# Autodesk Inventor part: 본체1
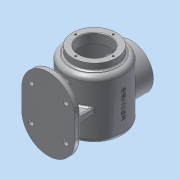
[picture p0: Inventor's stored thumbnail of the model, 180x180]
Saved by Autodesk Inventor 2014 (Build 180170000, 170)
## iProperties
Created: 2023-01
Part Number: 본체1
Material: 알루미늄 6061
Document SubType Name: Modeling
Designer: dg
Density: 2.71 g/cm^3
Appearance: 알루미늄 - 평지
Mass: 1027.11 g
Surface Area: 1161.19 cm^2
Volume: 379.006 cm^3
Author: dg
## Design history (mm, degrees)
sketch "스케치1"
  geometry: C1 r 50 at (0, 0); 1 further point
  constraints: 1 centre point, 1 coincident
  dimensions: "d0" = 100 diameter of C1
extrude "돌출1" new body sketch "스케치1" stored distance "d1" = 122; taper "d2" = 0 deg
sketch "스케치2"
  geometry: L1 (50, -61)-(-50, -61) reference; L2 (-50, -61)-(-50, 61) reference; L3 (-50, 61)-(50, 61) reference; L4 (50, 61)-(50, -61) reference; L5 (0, 61)-(0, -61); L6 (50, -50.087)-(50, -61); L7 (50, -61)-(0, -61); A1 r 120 centre (0, 59) between (0, -61) and (50, -50.087); 1 further point
  constraints: 6 end point, 3 midpoint, 2 collinear, 2 point on circle, 2 point on line, 2 tangent, 1 centre point
  dimensions: "d3" = 240 diameter of A1
revolve "회전1" sketch "스케치2" stored, may be unused: angle "d4" = 90 deg
sketch "스케치3"
  geometry: L1 (-50, -50.087)-(-50, 61) reference; L2 (-50, 61)-(50, 61) reference; L3 (50, 61)-(50, -50.087) reference; L4 (0, 61)-(0, -61); L5 (50, 49)-(38, 49); L6 (38, 49)-(38, 61); L7 (50, 49)-(50, 61); L8 (50, 61)-(38, 61); L9 (27, 61)-(27, 44); L10 (27, 44)-(42, 44); L11 (45, 41)-(45, -45.202); L12 (50, -50.087)-(-50, -50.087) reference; L13 (27, 61)-(0, 61); A1 r 120 centre (0, 59) between (0, -61) and (50, -50.087) reference; A2 r 120 centre (0, 59) between (-50, -50.087) and (0, -61) reference; A3 r 3 centre (42, 41) between (45, 41) and (42, 44); A4 r 120 centre (0, 64) between (0, -56) and (43.077, -48.002); A5 r 3 centre (42, -45.202) between (43.077, -48.002) and (45, -45.202); 2 further points
  constraints: 18 end point, 7 point on circle, 6 point on line, 4 perpendicular, 4 tangent, 3 centre point, 3 parallel, 2 collinear, 1 midpoint
  dimensions: "d5" = 76 diameter of L6 L4; "d6" = 110 distance from line of L4.end L5; "d10" = 90 diameter of L11 L4; "d11" = 17 distance between parallel lines of L2 L10; "d12" = 54 diameter of L9 L4; "d103" = 120 radius of A4; "d104" = 125 distance of L4.end A4.centre; "d105" = 3 radius of A5; "d106" = 3 radius of A3
revolve "회전2" sketch "스케치3" stored, may be unused: angle "d16" = 90 deg
chamfer "모따기1" distance "d17" = 1; stored, may be unused: second distance "d18" = 2, angle "d19" = 45 deg
fillet "모깎기1" dims "d20" = 8
fillet "모깎기2" dims "d21" = 3
node "작업 평면1"
sketch "스케치4"
  geometry: 1 further point
node "작업 평면2"
sketch "스케치5"
  geometry: L1 (38, 61)-(-38, 61) reference; C1 r 38 at (0, -2); A1 r 120 centre (0, 59) between (-45, -52.243) and (45, -52.243) reference; 1 further point
  constraints: 1 centre point, 1 vertical alignment
  dimensions: "d24" = 63 distance from line of C1.centre L1; "d25" = 76 diameter of C1
extrude "돌출2" join sketch "스케치5" stored distance "d26" = 122; taper "d27" = 0 deg
sketch "스케치6"
  geometry: L1 (0, 15)-(0, -19); L2 (-46, 15)-(-46, -19); L3 (46, -19)-(46, 15); L4 (-35, 3)-(35, 3); L5 (35, 3)-(35, -7); L6 (35, -7)-(-35, -7); L7 (-35, -7)-(-35, 3); L8 (-35, 3)-(35, -7); L9 (35, 3)-(-35, -7); C1 r 38 at (0, -2) reference; C2 r 38 at (0, -2) reference; A1 r 46 centre (0, 15) between (46, 15) and (-46, 15); A2 r 46 centre (0, -19) between (-46, -19) and (46, -19); 1 further point
  constraints: 20 end point, 4 point on circle, 4 tangent, 3 midpoint, 3 parallel, 2 centre point, 1 horizontal, 1 perpendicular, 1 vertical
  dimensions: "d31" = 92 distance between parallel lines of L2 L3; "d32" = 70 distance between parallel lines of L7 L5; "d33" = 10 distance of L4.end L5.end; "d34" = 34 distance of L3.start L3.end
extrude "돌출3" join sketch "스케치6" distance "d35" = 10; taper "d36" = 0 deg
fillet "모깎기3" dims "d37" = 3
sketch "스케치7"
  geometry: L1 (-35, -3)-(35, -3); L2 (35, -3)-(35, 7); L3 (35, 7)-(-35, 7); L4 (-35, 7)-(-35, -3); L5 (-35, -3)-(35, 7); L6 (35, -3)-(-35, 7); C1 r 38 at (0, 2) reference; 1 further point
  constraints: 12 end point, 2 parallel, 1 coincident, 1 horizontal, 1 midpoint, 1 perpendicular
  dimensions: "d38" = 10 distance between parallel lines of L1 L3; "d39" = 70 distance of L1.start L1.end
extrude "돌출4" join sketch "스케치7" stored distance "d40" = 10; taper "d41" = 0 deg
sketch "스케치9"
  geometry: L1 (-70, 58)-(-70, 3) reference; L2 (-70, 3)-(-50, 3) reference; L3 (-50, 3)-(-50, 41) reference; L4 (-42, 49)-(-41, 49) reference; L5 (-38, 52)-(-38, 61) reference; L6 (-38, 61)-(-28, 61) reference; L7 (-28, 61)-(-27, 60) reference; L8 (-27, 60)-(-27, 44) reference; L9 (-27, 44)-(-42, 44) reference; L10 (-45, 41)-(-45, -45.202) reference; L11 (45, -45.202)-(45, 41) reference; L12 (42, 44)-(27, 44) reference; L13 (27, 44)-(27, 60) reference; L14 (27, 60)-(28, 61) reference; L15 (28, 61)-(38, 61) reference; L16 (38, 61)-(38, 52) reference; L17 (41, 49)-(42, 49) reference; L18 (50, 41)-(50, 36) reference; L19 (50, 36)-(64, 36) reference; L20 (64, 36)-(64, -40) reference; L21 (64, -40)-(50, -40) reference; L22 (50, -40)-(50, -44.827) reference; L23 (-50, -44.827)-(-50, -7) reference; L24 (-50, -7)-(-70, -7) reference; L25 (-70, -7)-(-70, -62) reference; L26 (-73, -65)-(-80, -65) reference; L27 (-80, -65)-(-80, 61) reference; L28 (-80, 61)-(-73, 61) reference; L29 (-50, 32.641)-(-70, 38); A1 r 3 centre (-73, 58) between (-70, 58) and (-73, 61) reference; A2 r 8 centre (-42, 41) between (-42, 49) and (-50, 41) reference; A3 r 3 centre (-41, 52) between (-41, 49) and (-38, 52) reference; A4 r 3 centre (-42, 41) between (-42, 44) and (-45, 41) reference; A5 r 3 centre (42, 41) between (45, 41) and (42, 44) reference; A6 r 3 centre (41, 52) between (38, 52) and (41, 49) reference; A7 r 8 centre (42, 41) between (50, 41) and (42, 49) reference; A8 r 8 centre (42, -44.827) between (45, -52.243) and (50, -44.827) reference; A9 r 120 centre (0, 59) between (-45, -52.243) and (0, -61) reference; A10 r 120 centre (0, 59) between (0, -61) and (45, -52.243) reference; A11 r 8 centre (-42, -44.827) between (-50, -44.827) and (-45, -52.243) reference; A12 r 3 centre (-73, -62) between (-73, -65) and (-70, -62) reference; A13 r 3 centre (-42, -45.202) between (-45, -45.202) and (-43.077, -48.002) reference; A14 r 120 centre (0, 64) between (-43.077, -48.002) and (0, -56) reference; A15 r 120 centre (0, 64) between (0, -56) and (43.077, -48.002) reference; A16 r 3 centre (42, -45.202) between (43.077, -48.002) and (45, -45.202) reference; 1 further point
  constraints: 2 end point, 2 point on line
  dimensions: "d42" = 105 deg angle of L1 L29; "d98" = 23 distance from line of L28 L29.end
feature "리브1" sketch "스케치9" dims "d44" = 1, "d45" = 10, "d46" = 0, "d47" = 0, "d48" = 1, "d49" = 1
node "작업 평면3"
sketch "스케치10"
  geometry: C1 r 38 at (0, 0) reference; C2 r 27 at (0, 0); 1 further point
  constraints: 1 centre point, 1 coincident
  dimensions: "d51" = 54 diameter of C2
extrude "돌출5" cut sketch "스케치10" stored distance "d52" = 10; taper "d53" = 0 deg
sketch "스케치11" dims "d54" = 65
  geometry: C1 r 27 at (0, 0) reference; C2 r 38 at (0, 0) reference; C3 r 3.218 at (0, 32.5); 2 further points
  constraints: 2 vertical alignment, 1 centre point, 1 coincident, 2 other
hole "구멍1" sketch "스케치11" at (0, 32.5) diameter "d55" = 3.242; stored, may be unused: countersink angle "d59" = 90 deg, drill point angle "d61" = 118 deg; dims "d56" = 8, "d57" = 4, "d58" = 2, "d60" = 10
sketch "스케치12" dims "d65" = 65
  geometry: C1 r 38 at (0, 0) reference; C2 r 28 at (0, 0) reference; C3 r 3.222 at (0, 32.5); 1 further point
  constraints: 2 vertical alignment, 1 centre point, 1 coincident, 2 other
hole "구멍2" sketch "스케치12" at (0, 32.5) diameter "d66" = 3.242; stored, may be unused: countersink angle "d70" = 90 deg, drill point angle "d72" = 118 deg; dims "d67" = 8, "d68" = 4, "d69" = 2, "d71" = 10
fillet "모깎기4" dims "d76" = 3
fillet "모깎기5" dims "d77" = 3
chamfer "모따기2" distance "d78" = 1; stored, may be unused: second distance "d79" = 2, angle "d80" = 45 deg
node "작업 평면4"
sketch "스케치13"
  geometry: L1 (38, 61)-(-38, 61) reference; L2 (-80, -65)-(-80, -19) reference; 2 further points
  constraints: 1 other
  dimensions: "d82" = 63 distance from line of L1 point (0, -2); "d83" = 80 distance from line of L2 point (0, -2)
feature "엠보싱1" sketch "스케치13" dims "d5" = 76, "d6" = 110, "d10" = 90, "d11" = 17, "d12" = 54, "d84" = 0.5, "d85" = 0, "d103" = 120, "d104" = 125, "d105" = 3, "d106" = 3
sketch "스케치14"
  geometry: C1 r 4.5 at (-30, -30); C2 r 4.5 at (-30, 30); C3 r 4.5 at (30, -30); C4 r 4.5 at (30, 30); 1 further point
  constraints: 4 centre point, 3 equal radius
  dimensions: "d86" = 30 horizontal distance of point (0, 0) C1.centre; "d87" = 30 horizontal distance of point (0, 0) C1.centre; "d88" = 9 diameter of C1; "d89" = 30 horizontal distance of C2.centre point (0, 0); "d90" = 30 horizontal distance of point (0, 0) C2.centre; "d91" = 30 horizontal distance of point (0, 0) C3.centre; "d92" = 30 horizontal distance of point (0, 0) C3.centre; "d93" = 30 horizontal distance of point (0, 0) C4.centre; "d94" = 30 horizontal distance of point (0, 0) C4.centre
extrude "돌출6" cut sketch "스케치14" distance "d95" = 10; taper "d96" = 0 deg
node "작업 평면5"
fillet "모깎기6" dims "d99" = 3
fillet "모깎기7" dims "d100" = 3
node "솔리드1"
pattern_circular "원형 패턴1" dims angle "d63" = 360 deg
pattern_circular "원형 패턴2" dims angle "d74" = 360 deg
mirror "대칭2"
node "투영된 루프1"
node "투영된 루프2"
node "절단 모서리 투영1"
node "절단 모서리 투영2"
node "절단 모서리 투영4"
other parameters: "d23" = 64, "d50" = 0
